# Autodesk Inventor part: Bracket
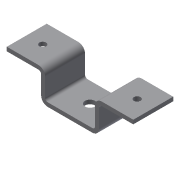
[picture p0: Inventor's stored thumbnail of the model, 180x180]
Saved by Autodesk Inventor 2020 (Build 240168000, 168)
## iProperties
Part Number: Bracket
Document SubType Name: Modeling
Created: 2003-01
Designer: Owner
Density: 1 g/cm^3
Material: Generic
Appearance: Default
Control State: 0
Master: False
Checked Out: False
Shininess: 64.0
Length Units: 11269
Angle Units: 11279
Time Units: 11290
Mass Units: 11283
Length Display Precision: 3
Angle Display Precision: 2
Compacted: True
Density: 0.0
Volumn: 0.0
Area: 0.0
PropertySet Name: Model Information
Author: Owner
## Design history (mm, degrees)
sketch "Sketch2"
  geometry: L1 (487.39, 112.858)-(199.89, 112.858); L2 (199.89, 112.858)-(199.89, -95.142); L3 (199.89, -95.142)-(-175.11, -95.142); L4 (-175.11, -95.142)-(-175.11, 112.858); L5 (-175.11, 112.858)-(-462.61, 112.858); L6 (-462.61, 82.858)-(-205.11, 82.858); L7 (-205.11, 82.858)-(-205.11, -125.142); L8 (-205.11, -125.142)-(229.89, -125.142); L9 (229.89, -125.142)-(229.89, 82.858); L10 (229.89, 82.858)-(487.39, 82.858); L11 (487.39, 112.858)-(487.39, 82.858); L12 (-462.61, 112.858)-(-462.61, 82.858)
  constraints: 24 end point, 5 parallel, 3 perpendicular, 2 collinear, 2 equal length, 1 horizontal, 4 other
  dimensions: "d0" = 375 distance between parallel lines of L4 L2; "d1" = 950 distance of L5.end L1.start; "d2" = 30 distance between parallel lines of L1 L10; "d3" = 238 distance between parallel lines of L5 L8
extrude "Extrusion1" new body sketch "Sketch2" stored distance "d4" = 300; taper "d5" = 0 deg
fillet "Fillet1" dims "d6" = 20
fillet "Fillet2" dims "d7" = 50
sketch "Sketch3"
  geometry: L1 (237.5, 300)-(0, 300) reference; L2 (0, 300)-(0, 0) reference; 1 further point
  dimensions: "d8" = 120 distance from line of L2 point (120, 150); "d9" = 150 distance from line of L1 point (120, 150)
hole "Hole1" sketch "Sketch3" at (120, 150) diameter "d10" = 50; stored, may be unused: countersink angle "d14" = 82 deg, drill point angle "d16" = 118 deg; dims "d11" = 6, "d12" = 4, "d13" = 2, "d15" = 8
pattern_linear "Rectangular Pattern1" dims "d19" = 710
sketch "Sketch4"
  geometry: L1 (0, -300)-(335, -300) reference; 1 further point
  dimensions: "d20" = 150 distance from line of L1 point (167.5, -150)
hole "Hole2" sketch "Sketch4" at (167.5, -150) diameter "d21" = 75; stored, may be unused: countersink angle "d25" = 82 deg, drill point angle "d27" = 118 deg; dims "d22" = 6, "d23" = 4, "d24" = 2, "d26" = 8
body "Solid1"
